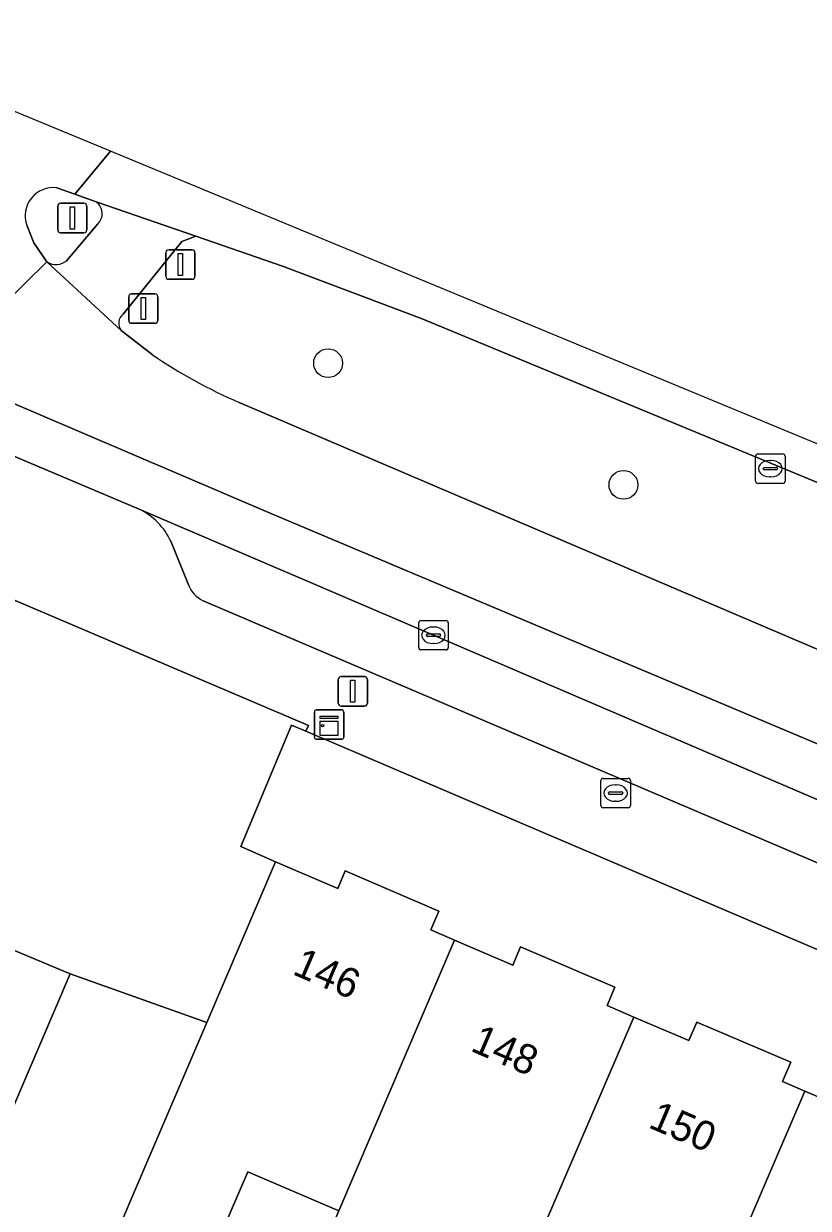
# Model space of a CAD drawing. Extents: x 162073 to 163043, y 381818 to 382561.
# Drawn here: x 162392.25 to 162418.89, y 382521.02 to 382561.22 of the extents above; entities that cross this region are included whole.
import ezdxf

# ---------------------------------------------------------------- set-up
doc = ezdxf.new("R2010")
doc.units = 0
for name, color, linetype in [('IMGEO_Berm_groen', 7, 'Continuous'), ('IMGEO_Boom', 7, 'Continuous'), ('IMGEO_Brandkraan', 7, 'Continuous'), ('IMGEO_Erf', 7, 'Continuous'), ('IMGEO_Fietspad_gesloten', 7, 'Continuous'), ('IMGEO_Kast', 7, 'Continuous'), ('IMGEO_Kolk', 7, 'Continuous'), ('IMGEO_Lichtmast', 7, 'Continuous'), ('IMGEO_Pand', 7, 'Continuous'), ('IMGEO_Pand_nummerreeks', 7, 'Continuous'), ('IMGEO_Parkeervlak_open', 7, 'Continuous'), ('IMGEO_Rijbaan_lokaal_gesloten', 7, 'Continuous'), ('IMGEO_Rioolput', 7, 'Continuous'), ('IMGEO_Verkeerseiland_gesloten', 7, 'Continuous'), ('IMGEO_Verkeersregelinstallatiepaal', 7, 'Continuous'), ('IMGEO_Voetpad_open', 7, 'Continuous')]:
    doc.layers.add(name, color=color, linetype=linetype)

msp = doc.modelspace()

# ---------------------------------------------------------------- linework, layer by layer
at = {"layer": 'IMGEO_Berm_groen'}
for points in [[(162405.776, 382551.203), (162401.042, 382552.994), (162398.102, 382554.01), (162397.626, 382553.828), (162395.634, 382551.362)], [(162465.868, 382526.328), (162405.776, 382551.203)], [(162395.566, 382550.807), (162396.621, 382549.991)], [(162399.569, 382548.369), (162463.588, 382521.054)]]:
    msp.add_lwpolyline(points, dxfattribs=at)
for centre, radius, start, end in [((162395.864, 382551.052), 0.386, 126.5961, 219.4335), ((162406.139, 382563.799), 16.771, 235.4228, 246.9377)]:
    msp.add_arc(centre, radius, start, end, dxfattribs=at)
at = {"layer": 'IMGEO_Boom'}
for centre in [(162402.588, 382549.697), (162412.614, 382545.569)]:
    msp.add_circle(centre, 0.489, dxfattribs=at)
at = {"layer": 'IMGEO_Brandkraan'}
for p, q in [((162411.849, 382534.686), (162411.849, 382535.538)), ((162411.924, 382535.612), (162412.776, 382535.612)), ((162412.85, 382535.538), (162412.85, 382534.686)), ((162412.108, 382535.106), (162412.108, 382535.118)), ((162412.546, 382535.069), (162412.148, 382535.069)), ((162412.151, 382535.155), (162412.549, 382535.155)), ((162412.337, 382535.392), (162412.362, 382535.392)), ((162412.592, 382535.118), (162412.592, 382535.106)), ((162412.776, 382534.612), (162411.924, 382534.612)), ((162412.36, 382534.832), (162412.335, 382534.832))]:
    msp.add_line(p, q, dxfattribs=at)
for points in [[(162411.849, 382534.686), (162411.849, 382535.538)], [(162411.924, 382535.612), (162412.776, 382535.612)], [(162412.85, 382535.538), (162412.85, 382534.686)], [(162412.776, 382534.612), (162411.924, 382534.612)]]:
    msp.add_lwpolyline(points, dxfattribs=at)
for centre, radius, start, end in [((162411.926, 382535.536), 0.0765, 91.552, 178.448), ((162411.926, 382535.536), 0.0765, 91.552, 178.448), ((162412.774, 382535.536), 0.0765, 1.552, 88.448), ((162412.774, 382535.536), 0.0765, 1.552, 88.448), ((162412.148, 382535.115), 0.0403, 85.8775, 175.7526), ((162412.145, 382535.105), 0.0366, 178.938, 274.7102), ((162412.549, 382535.112), 0.043, 264.8664, 352.4533), ((162412.553, 382535.117), 0.0386, 1.7309, 96.639), ((162411.926, 382534.688), 0.0765, 181.552, 268.448), ((162411.926, 382534.688), 0.0765, 181.552, 268.448), ((162412.774, 382534.688), 0.0765, 271.552, 358.448), ((162412.774, 382534.688), 0.0765, 271.552, 358.448)]:
    msp.add_arc(centre, radius, start, end, dxfattribs=at)
for centre, major_axis, ratio, start_param, end_param in [((162412.336, 382535.112), (-0.387, 0.002), 0.722429, 4.712389, 7.853982), ((162412.361, 382535.112), (-0.39, 0.002), 0.717154, 1.570796, 4.712389)]:
    msp.add_ellipse(centre, major_axis=major_axis, ratio=ratio, start_param=start_param, end_param=end_param, dxfattribs=at)
at = {"layer": 'IMGEO_Erf'}
for points in [[(162458.224, 382513.15), (162401.834, 382537.213), (162401.347, 382537.421), (162399.626, 382533.294), (162400.803, 382532.782), (162402.914, 382531.879), (162403.167, 382532.471), (162406.345, 382531.111), (162406.071, 382530.47), (162406.874, 382530.126), (162408.857, 382529.278), (162409.122, 382529.896), (162412.325, 382528.526), (162412.058, 382527.902), (162412.97, 382527.512), (162414.832, 382526.715), (162415.102, 382527.345), (162418.294, 382525.98), (162418.014, 382525.326), (162418.777, 382525), (162420.85, 382524.113)], [(162420.806, 382513.257), (162417.404, 382514.718), (162416.091, 382514.196), (162414.438, 382514.908), (162414.833, 382515.826), (162411.455, 382517.277), (162410.142, 382516.755), (162408.627, 382517.407), (162408.489, 382517.466), (162408.884, 382518.385), (162405.46, 382519.855), (162404.147, 382519.334), (162402.555, 382520.019), (162402.948, 382520.938), (162399.859, 382522.267), (162396.707, 382514.939), (162393.719, 382516.224), (162392.996, 382513.631), (162392.481, 382501.527), (162406.489, 382500.801), (162406.644, 382503.357), (162410.442, 382503.127), (162414.648, 382502.872), (162414.497, 382500.375)]]:
    msp.add_lwpolyline(points, dxfattribs=at)
at = {"layer": 'IMGEO_Fietspad_gesloten'}
msp.add_lwpolyline([(162474.232, 382512.536), (162462.251, 382518.093), (162461.716, 382518.341), (162449.428, 382523.464), (162428.379, 382532.911), (162400.701, 382544.578), (162389.28, 382549.444), (162388.63, 382547.92), (162390.424, 382547.177), (162390.652, 382547.077), (162396.172, 382544.74), (162406.166, 382540.468), (162422.059, 382533.658), (162440.766, 382525.667), (162449.876, 382521.796), (162458.169, 382518.24), (162460.293, 382517.31), (162464.872, 382515.121), (162468.875, 382513.382), (162485.643, 382505.284)], dxfattribs=at)
at = {"layer": 'IMGEO_Kast'}
for p, q in [((162402.123, 382537.011), (162402.123, 382537.852)), ((162402.123, 382537.852), (162402.123, 382537.011)), ((162402.198, 382537.936), (162403.039, 382537.936)), ((162403.039, 382537.936), (162402.198, 382537.936)), ((162403.123, 382537.861), (162403.123, 382537.02)), ((162403.123, 382537.02), (162403.123, 382537.861)), ((162403.048, 382536.936), (162402.207, 382536.936)), ((162402.207, 382536.936), (162403.048, 382536.936))]:
    msp.add_line(p, q, dxfattribs=at)
for points in [[(162402.318, 382537.726), (162402.918, 382537.726), (162402.918, 382537.641), (162402.318, 382537.641), (162402.318, 382537.726)], [(162402.318, 382537.551), (162402.918, 382537.551), (162402.918, 382537.062), (162402.318, 382537.062), (162402.318, 382537.551)]]:
    msp.add_lwpolyline(points, dxfattribs=at)
msp.add_circle((162402.402, 382537.4), 0.0377, dxfattribs=at)
for centre, start, end in [((162402.201, 382537.858), 92.4484, 184.2845), ((162402.201, 382537.858), 92.4484, 184.2845), ((162403.045, 382537.858), 2.4484, 94.2845), ((162403.045, 382537.858), 2.4484, 94.2845), ((162402.201, 382537.014), 182.4484, 274.2845), ((162402.201, 382537.014), 182.4484, 274.2845), ((162403.045, 382537.014), 272.4484, 4.2845), ((162403.045, 382537.014), 272.4484, 4.2845)]:
    msp.add_arc(centre, 0.0779, start, end, dxfattribs=at)
at = {"layer": 'IMGEO_Kolk'}
for p, q in [((162405.664, 382540.041), (162405.664, 382540.893)), ((162405.739, 382540.967), (162406.591, 382540.967)), ((162406.152, 382540.747), (162406.177, 382540.747)), ((162406.665, 382540.893), (162406.665, 382540.041)), ((162405.923, 382540.461), (162405.923, 382540.473)), ((162406.361, 382540.424), (162405.963, 382540.424)), ((162405.966, 382540.51), (162406.364, 382540.51)), ((162406.407, 382540.473), (162406.407, 382540.461)), ((162406.591, 382539.967), (162405.739, 382539.967)), ((162406.175, 382540.187), (162406.15, 382540.187))]:
    msp.add_line(p, q, dxfattribs=at)
for points in [[(162405.664, 382540.041), (162405.664, 382540.893)], [(162405.739, 382540.967), (162406.591, 382540.967)], [(162406.665, 382540.893), (162406.665, 382540.041)], [(162406.591, 382539.967), (162405.739, 382539.967)]]:
    msp.add_lwpolyline(points, dxfattribs=at)
for centre, radius, start, end in [((162405.741, 382540.891), 0.0765, 91.552, 178.448), ((162405.741, 382540.891), 0.0765, 91.552, 178.448), ((162406.589, 382540.891), 0.0765, 1.552, 88.448), ((162406.589, 382540.891), 0.0765, 1.552, 88.448), ((162405.963, 382540.47), 0.0403, 85.8775, 175.7526), ((162405.96, 382540.46), 0.0366, 178.938, 274.7102), ((162406.364, 382540.467), 0.043, 264.8664, 352.4533), ((162406.368, 382540.472), 0.0386, 1.7309, 96.639), ((162405.741, 382540.043), 0.0765, 181.552, 268.448), ((162405.741, 382540.043), 0.0765, 181.552, 268.448), ((162406.589, 382540.043), 0.0765, 271.552, 358.448), ((162406.589, 382540.043), 0.0765, 271.552, 358.448)]:
    msp.add_arc(centre, radius, start, end, dxfattribs=at)
for centre, major_axis, ratio, start_param, end_param in [((162406.151, 382540.467), (-0.387, 0.002), 0.722429, 4.712389, 7.853982), ((162406.176, 382540.467), (-0.39, 0.002), 0.717154, 1.570796, 4.712389)]:
    msp.add_ellipse(centre, major_axis=major_axis, ratio=ratio, start_param=start_param, end_param=end_param, dxfattribs=at)
at = {"layer": 'IMGEO_Lichtmast'}
for p, q in [((162393.51, 382555.125), (162394.3, 382555.125)), ((162394.3, 382555.125), (162393.51, 382555.125)), ((162393.41, 382554.225), (162393.41, 382555.025)), ((162393.41, 382555.025), (162393.41, 382554.225)), ((162394.4, 382555.025), (162394.4, 382554.225)), ((162394.4, 382554.225), (162394.4, 382555.025)), ((162394.3, 382554.125), (162393.51, 382554.125)), ((162393.51, 382554.125), (162394.3, 382554.125)), ((162403.031, 382539.066), (162403.821, 382539.066)), ((162403.821, 382539.066), (162403.031, 382539.066)), ((162402.931, 382538.166), (162402.931, 382538.966)), ((162402.931, 382538.966), (162402.931, 382538.166)), ((162403.921, 382538.966), (162403.921, 382538.166)), ((162403.921, 382538.166), (162403.921, 382538.966)), ((162403.821, 382538.066), (162403.031, 382538.066)), ((162403.031, 382538.066), (162403.821, 382538.066))]:
    msp.add_line(p, q, dxfattribs=at)
for points in [[(162393.83, 382555), (162393.98, 382555), (162393.98, 382554.25), (162393.83, 382554.25), (162393.83, 382555)], [(162403.351, 382538.941), (162403.501, 382538.941), (162403.501, 382538.191), (162403.351, 382538.191), (162403.351, 382538.941)]]:
    msp.add_lwpolyline(points, dxfattribs=at)
for centre, start, end in [((162393.51, 382555.025), 90, 180), ((162393.51, 382555.025), 90, 180), ((162394.3, 382555.025), 0, 90), ((162394.3, 382555.025), 360, 90), ((162393.51, 382554.225), 180, 270), ((162393.51, 382554.225), 180, 270), ((162394.3, 382554.225), 270, 0), ((162394.3, 382554.225), 270, 0), ((162403.031, 382538.966), 90, 180), ((162403.031, 382538.966), 90, 180), ((162403.821, 382538.966), 0, 90), ((162403.821, 382538.966), 360, 90), ((162403.031, 382538.166), 180, 270), ((162403.031, 382538.166), 180, 270), ((162403.821, 382538.166), 270, 0), ((162403.821, 382538.166), 270, 0)]:
    msp.add_arc(centre, 0.1, start, end, dxfattribs=at)
at = {"layer": 'IMGEO_Pand'}
msp.add_lwpolyline([(162379.594, 382538.274), (162377.78, 382536.852), (162383.693, 382529.374), (162384.016, 382529.006), (162387.393, 382525.154), (162387.022, 382524.835), (162389.19, 382522.297), (162391.873, 382524.4), (162393.833, 382528.975), (162391.042, 382530.146), (162389.838, 382531.731), (162387.132, 382535.191), (162385.746, 382536.964), (162386.534, 382537.58), (162383.578, 382541.341)], dxfattribs=at)
for points in [[(162406.874, 382530.126), (162406.071, 382530.47), (162406.345, 382531.111), (162403.167, 382532.471), (162402.914, 382531.879), (162400.803, 382532.782), (162398.47, 382527.329), (162396.504, 382522.733), (162393.719, 382516.224), (162396.707, 382514.939), (162399.859, 382522.267), (162402.948, 382520.938)], [(162412.97, 382527.512), (162412.058, 382527.902), (162412.325, 382528.526), (162409.122, 382529.896), (162408.857, 382529.278), (162406.874, 382530.126), (162402.948, 382520.938), (162402.555, 382520.019), (162404.147, 382519.334), (162405.46, 382519.855), (162408.884, 382518.385), (162408.489, 382517.466), (162408.627, 382517.407)], [(162408.627, 382517.407), (162410.142, 382516.755), (162411.455, 382517.277), (162414.833, 382515.826), (162418.777, 382525), (162418.014, 382525.326), (162418.294, 382525.98), (162415.102, 382527.345), (162414.832, 382526.715), (162412.97, 382527.512)], [(162420.548, 382512.279), (162424.876, 382522.39), (162424.013, 382522.759), (162424.282, 382523.388), (162421.119, 382524.741), (162420.85, 382524.113), (162418.777, 382525), (162414.833, 382515.826), (162414.438, 382514.908), (162416.091, 382514.196), (162417.404, 382514.718), (162420.806, 382513.257), (162420.411, 382512.338)]]:
    msp.add_lwpolyline(points, close=True, dxfattribs=at)
at = {"layer": 'IMGEO_Parkeervlak_open'}
for points in [[(162401.347, 382537.421), (162401.834, 382537.213), (162401.922, 382537.401), (162383.831, 382545.112), (162380.177, 382543.395), (162379.136, 382542.671), (162375.557, 382539.591), (162377.78, 382536.852), (162379.594, 382538.274)], [(162449.876, 382521.796), (162440.766, 382525.667), (162422.059, 382533.658), (162406.166, 382540.468), (162396.172, 382544.74)], [(162397.245, 382543.655), (162397.847, 382542.182)], [(162398.353, 382541.637), (162441.17, 382523.381), (162445.322, 382521.559), (162446.259, 382521.175)], [(162383.578, 382541.341), (162386.534, 382537.58), (162385.746, 382536.964), (162387.132, 382535.191), (162389.838, 382531.731), (162391.042, 382530.146), (162393.833, 382528.975), (162398.47, 382527.329), (162400.803, 382532.782), (162399.626, 382533.294), (162401.347, 382537.421)]]:
    msp.add_lwpolyline(points, dxfattribs=at)
for centre, radius, start, end in [((162395.265, 382542.769), 2.169, 24.0904, 65.2723), ((162398.751, 382542.514), 0.963, 200.1666, 245.5832)]:
    msp.add_arc(centre, radius, start, end, dxfattribs=at)
at = {"layer": 'IMGEO_Rijbaan_lokaal_gesloten'}
for points in [[(162393.38, 382555.645), (162393.994, 382555.427), (162395.197, 382556.889), (162384.743, 382561.216), (162376.631, 382554.798)], [(162376.631, 382554.798), (162378.282, 382554.129), (162380.741, 382553.081), (162388.344, 382549.843), (162389.28, 382549.444), (162393.046, 382553.133), (162392.595, 382553.778), (162392.36, 382554.38)], [(162396.621, 382549.991), (162395.566, 382550.807), (162393.046, 382553.133), (162389.28, 382549.444), (162400.701, 382544.578), (162428.379, 382532.911), (162449.428, 382523.464), (162461.716, 382518.341), (162462.251, 382518.093), (162463.588, 382521.054)], [(162463.588, 382521.054), (162399.569, 382548.369)]]:
    msp.add_lwpolyline(points, dxfattribs=at)
msp.add_lwpolyline([(162466.322, 382527.451), (162395.197, 382556.889), (162393.994, 382555.427), (162394.71, 382555.173), (162398.102, 382554.01), (162401.042, 382552.994), (162405.776, 382551.203), (162465.868, 382526.328)], close=True, dxfattribs=at)
for centre, radius, start, end in [((162393.26, 382554.698), 0.955, 82.7969, 199.443), ((162406.139, 382563.799), 16.771, 235.4228, 246.9377)]:
    msp.add_arc(centre, radius, start, end, dxfattribs=at)
at = {"layer": 'IMGEO_Rioolput'}
for p, q in [((162417.102, 382545.693), (162417.102, 382546.545)), ((162417.177, 382546.619), (162418.029, 382546.619)), ((162417.59, 382546.399), (162417.615, 382546.399)), ((162418.103, 382546.545), (162418.103, 382545.693)), ((162417.361, 382546.113), (162417.361, 382546.125)), ((162417.799, 382546.076), (162417.401, 382546.076)), ((162417.404, 382546.162), (162417.802, 382546.162)), ((162417.845, 382546.125), (162417.845, 382546.113)), ((162418.029, 382545.619), (162417.177, 382545.619)), ((162417.613, 382545.839), (162417.588, 382545.839))]:
    msp.add_line(p, q, dxfattribs=at)
for points in [[(162417.102, 382545.693), (162417.102, 382546.545)], [(162417.177, 382546.619), (162418.029, 382546.619)], [(162418.103, 382546.545), (162418.103, 382545.693)], [(162418.029, 382545.619), (162417.177, 382545.619)]]:
    msp.add_lwpolyline(points, dxfattribs=at)
for centre, radius, start, end in [((162417.179, 382546.543), 0.0765, 91.552, 178.448), ((162417.179, 382546.543), 0.0765, 91.552, 178.448), ((162418.027, 382546.543), 0.0765, 1.552, 88.448), ((162418.027, 382546.543), 0.0765, 1.552, 88.448), ((162417.401, 382546.122), 0.0403, 85.8775, 175.7526), ((162417.398, 382546.112), 0.0366, 178.938, 274.7102), ((162417.802, 382546.119), 0.043, 264.8664, 352.4533), ((162417.806, 382546.124), 0.0386, 1.7309, 96.639), ((162417.179, 382545.695), 0.0765, 181.552, 268.448), ((162417.179, 382545.695), 0.0765, 181.552, 268.448), ((162418.027, 382545.695), 0.0765, 271.552, 358.448), ((162418.027, 382545.695), 0.0765, 271.552, 358.448)]:
    msp.add_arc(centre, radius, start, end, dxfattribs=at)
for centre, major_axis, ratio, start_param, end_param in [((162417.589, 382546.119), (-0.387, 0.002), 0.722429, 4.712389, 7.853982), ((162417.614, 382546.119), (-0.39, 0.002), 0.717154, 1.570796, 4.712389)]:
    msp.add_ellipse(centre, major_axis=major_axis, ratio=ratio, start_param=start_param, end_param=end_param, dxfattribs=at)
at = {"layer": 'IMGEO_Verkeerseiland_gesloten'}
for points in [[(162394.71, 382555.173), (162393.994, 382555.427), (162393.38, 382555.645)], [(162392.36, 382554.38), (162392.595, 382553.778), (162393.046, 382553.133)], [(162393.723, 382553.187), (162394.775, 382554.423)]]:
    msp.add_lwpolyline(points, dxfattribs=at)
for centre, radius, start, end in [((162393.26, 382554.698), 0.955, 82.7969, 199.443), ((162394.424, 382554.77), 0.494, 315.2972, 54.6093), ((162393.349, 382553.605), 0.561, 237.3256, 311.7953)]:
    msp.add_arc(centre, radius, start, end, dxfattribs=at)
at = {"layer": 'IMGEO_Verkeersregelinstallatiepaal'}
for p, q in [((162397.179, 382553.545), (162397.969, 382553.545)), ((162397.969, 382553.545), (162397.179, 382553.545)), ((162397.079, 382552.645), (162397.079, 382553.445)), ((162397.079, 382553.445), (162397.079, 382552.645)), ((162398.069, 382553.445), (162398.069, 382552.645)), ((162398.069, 382552.645), (162398.069, 382553.445)), ((162397.969, 382552.545), (162397.179, 382552.545)), ((162397.179, 382552.545), (162397.969, 382552.545)), ((162395.82, 382551.151), (162395.82, 382551.951)), ((162395.82, 382551.951), (162395.82, 382551.151)), ((162395.92, 382552.051), (162396.71, 382552.051)), ((162396.71, 382552.051), (162395.92, 382552.051)), ((162396.81, 382551.951), (162396.81, 382551.151)), ((162396.81, 382551.151), (162396.81, 382551.951)), ((162396.71, 382551.051), (162395.92, 382551.051)), ((162395.92, 382551.051), (162396.71, 382551.051))]:
    msp.add_line(p, q, dxfattribs=at)
for points in [[(162397.499, 382553.42), (162397.649, 382553.42), (162397.649, 382552.67), (162397.499, 382552.67), (162397.499, 382553.42)], [(162396.24, 382551.926), (162396.39, 382551.926), (162396.39, 382551.176), (162396.24, 382551.176), (162396.24, 382551.926)]]:
    msp.add_lwpolyline(points, dxfattribs=at)
for centre, start, end in [((162397.179, 382553.445), 90, 180), ((162397.179, 382553.445), 90, 180), ((162397.969, 382553.445), 0, 90), ((162397.969, 382553.445), 360, 90), ((162397.179, 382552.645), 180, 270), ((162397.179, 382552.645), 180, 270), ((162397.969, 382552.645), 270, 0), ((162397.969, 382552.645), 270, 0), ((162395.92, 382551.951), 90, 180), ((162395.92, 382551.951), 90, 180), ((162396.71, 382551.951), 0, 90), ((162396.71, 382551.951), 360, 90), ((162395.92, 382551.151), 180, 270), ((162395.92, 382551.151), 180, 270), ((162396.71, 382551.151), 270, 0), ((162396.71, 382551.151), 270, 0)]:
    msp.add_arc(centre, 0.1, start, end, dxfattribs=at)
at = {"layer": 'IMGEO_Voetpad_open'}
for points in [[(162395.634, 382551.362), (162397.626, 382553.828), (162398.102, 382554.01), (162394.71, 382555.173)], [(162394.775, 382554.423), (162393.723, 382553.187)], [(162393.046, 382553.133), (162395.566, 382550.807)], [(162396.172, 382544.74), (162390.652, 382547.077), (162390.424, 382547.177)], [(162377.131, 382544.985), (162383.831, 382545.112), (162401.922, 382537.401), (162401.834, 382537.213), (162458.224, 382513.15)], [(162397.847, 382542.182), (162397.245, 382543.655)], [(162446.259, 382521.175), (162445.322, 382521.559), (162445.151, 382521.079), (162440.952, 382522.88), (162441.17, 382523.381), (162398.353, 382541.637)], [(162406.489, 382500.801), (162392.481, 382501.527), (162392.996, 382513.631), (162393.719, 382516.224), (162396.504, 382522.733), (162398.47, 382527.329), (162393.833, 382528.975), (162391.873, 382524.4), (162389.19, 382522.297), (162387.7, 382521.135), (162384.517, 382518.646), (162381.325, 382516.15), (162378.502, 382513.68), (162380.622, 382511.882), (162381.244, 382511.476), (162383.191, 382510.204), (162385.436, 382509.111), (162388.384, 382508.004), (162391.687, 382507.612), (162391.079, 382501.6), (162390.14, 382501.726), (162390.073, 382500.303)]]:
    msp.add_lwpolyline(points, dxfattribs=at)
for centre, radius, start, end in [((162394.424, 382554.77), 0.494, 315.2972, 54.6093), ((162393.349, 382553.605), 0.561, 237.3256, 311.7953), ((162395.864, 382551.052), 0.386, 126.5961, 219.4335), ((162395.265, 382542.769), 2.169, 24.0904, 65.2723), ((162398.751, 382542.514), 0.963, 200.1666, 245.5832)]:
    msp.add_arc(centre, radius, start, end, dxfattribs=at)

# ---------------------------------------------------------------- texts
at = {"layer": 'IMGEO_Pand_nummerreeks'}
for s, rotation, p in [('146', 336.715, (162401.343, 382528.979)), ('148', 336.715, (162407.384, 382526.379)), ('150', 336.7173, (162413.421, 382523.781))]:
    msp.add_text(s, height=1, rotation=rotation, dxfattribs=at).set_placement(p)

doc.saveas('drawing.dxf')
